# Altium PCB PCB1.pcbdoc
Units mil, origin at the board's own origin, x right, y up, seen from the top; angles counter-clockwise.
Board outline 4214 x 1585.88 mil, 2 copper layers (Top Layer, Bottom Layer); 84 components, 62 nets, 353 pads, 138 vias.
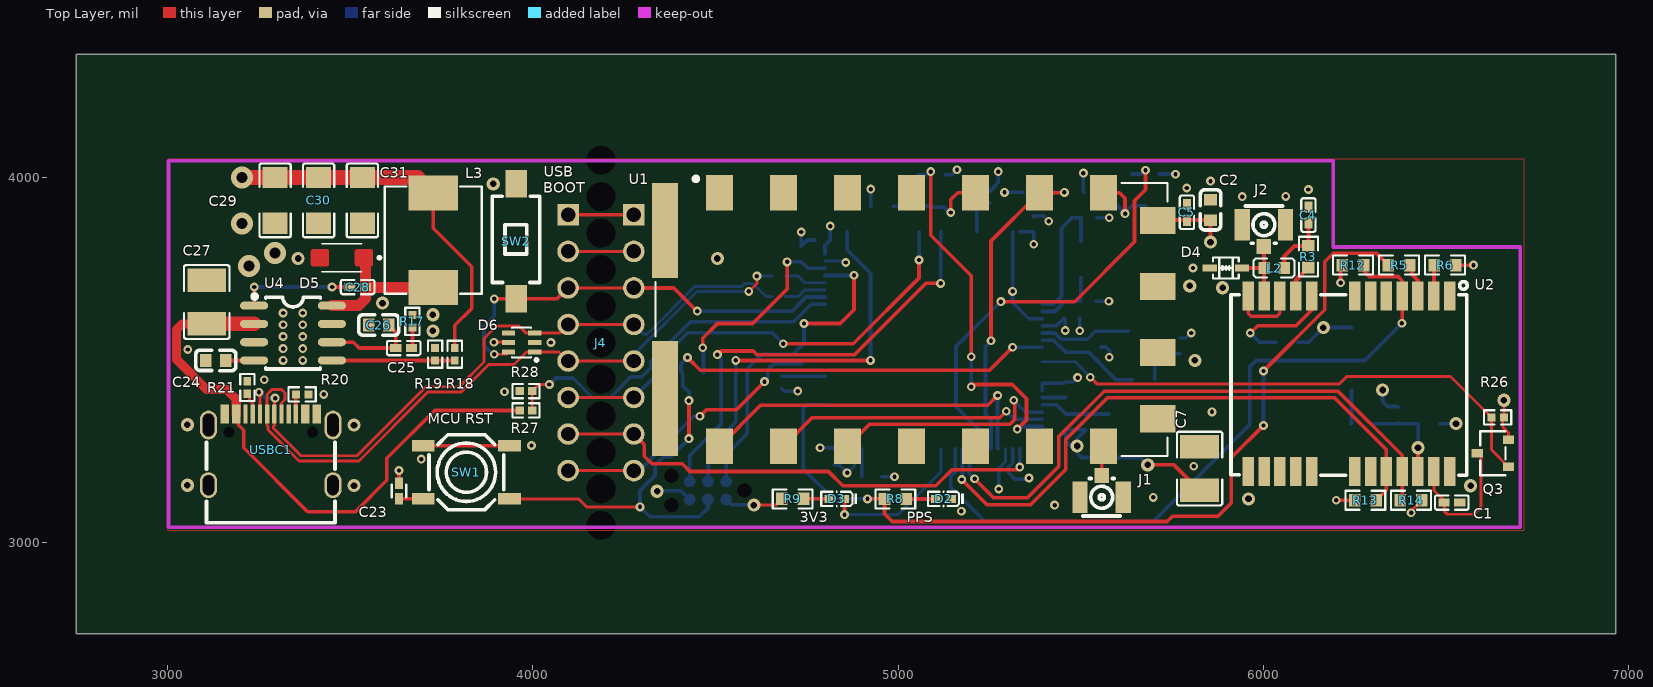
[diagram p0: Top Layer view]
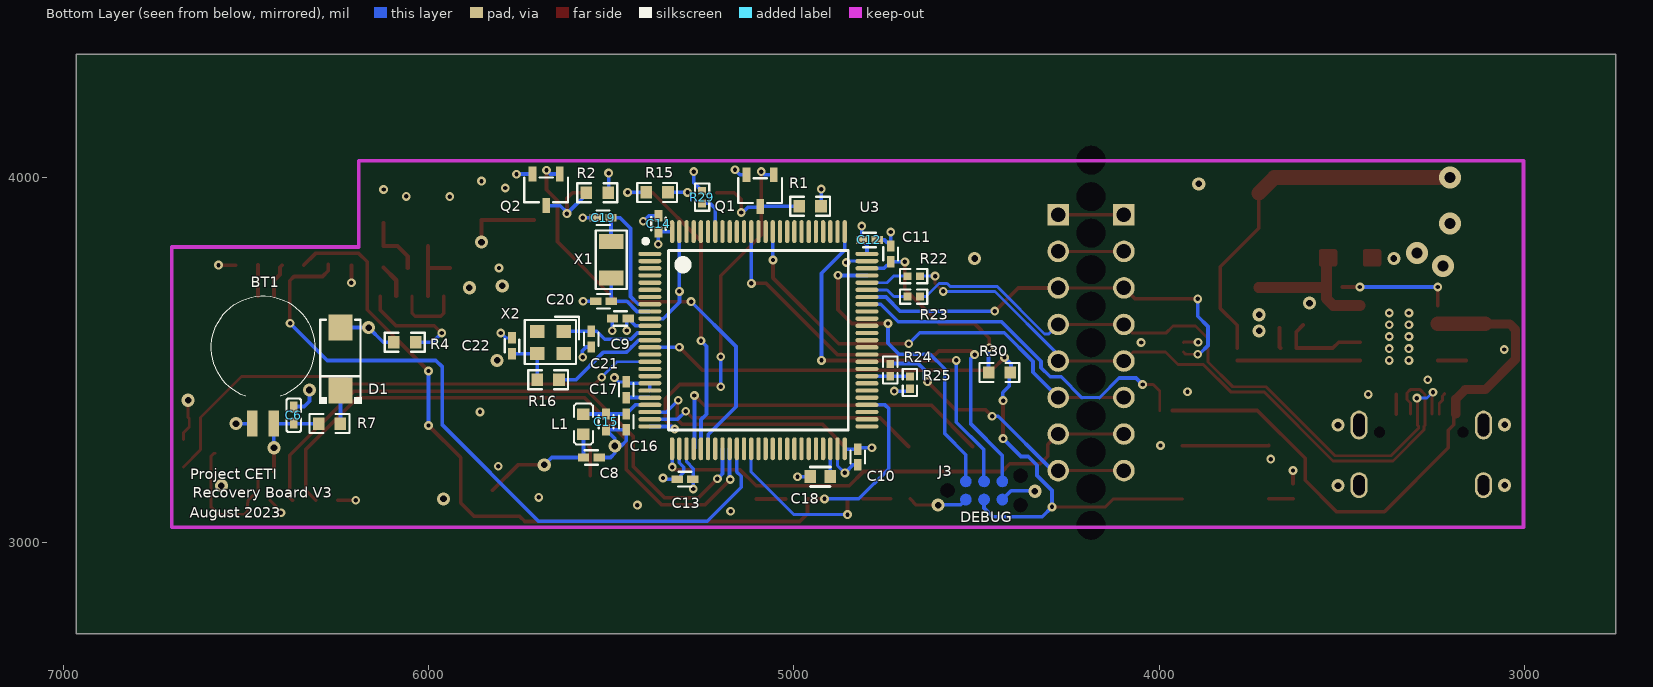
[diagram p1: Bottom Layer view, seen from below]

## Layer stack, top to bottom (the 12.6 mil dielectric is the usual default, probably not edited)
Top Layer: signal copper (thickness not stored)
Dielectric: dielectric 12.6, FR-4, Dk 4.8
Bottom Layer: signal copper (thickness not stored)

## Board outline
6964,2750 2750,2750 2750,4335.88 6964,4335.88

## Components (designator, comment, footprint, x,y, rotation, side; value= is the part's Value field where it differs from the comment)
BT1 "MS621FE-FL11E" MS621FE-FL11E 6453,3325 r180 bottom
C1 "100nF" C0402 6515.46,3109 r180 top
C2 "10uF" C0603 5855,3910 r270 top
C4 "47pF" C0402 6123,3896 r270 top
C5 "100nF" C0402 5790.46,3903.46 r270 top
C6 "1uF" C0402 6369,3348 r270 bottom
C7 "100uF" C1210 5825,3202 r90 top
C8 "100nF" C0402 5554.33,3232.25 r0 bottom
C9 "100nF" C0402 5474.79,3612.79 r180 bottom
C10 "100nF" C0402 4824.79,3233.79 r90 bottom
C11 "100nF" C0402 4734.79,3789.79 r270 bottom
C12 "100nF" C0402 4792.79,3827.79 r0 bottom
C13 "100nF" C0402 5298,3173 r180 bottom
C14 "100nF" C0402 5370.33,3872.25 r270 bottom
C15 "1uF" C0402 5513.79,3329.79 r90 bottom
C16 "10nF" C0402 5458.79,3329.79 r90 bottom
C17 "100nF" C0402 5458.79,3417.79 r270 bottom
C18 "4.7uF" C0603 4927.79,3179.79 r180 bottom
C19 "15pF" C0402 5521.79,3888.79 r180 bottom
C20 "15pF" C0402 5520.79,3659.79 r180 bottom
C21 "6pF" C0402 5554.38,3556.2 r90 bottom
C22 "6pF" C0402 5771.38,3538.2 r270 bottom
C23 "100nF" C0402 3633.16,3140.54 r270 top
C24 "CC0603KRX7R9BB822" C0603 3132,3498 r0 top
C25 "0402B102K500NT" C0402 3646,3532 r180 top
C26 "0603CG6R8C500NT" C0603 3578,3595 r0 top
C27 "GCM32ER71C226KE19L" C1210 3107,3658 r270 top
C28 "V104K0402X5R250NBT" C0402 3520,3699 r0 top
C29 "CL31A476MPHNNNE" C1206 3294,3936 r90 top
C30 "CL31A476MPHNNNE" C1206 3413,3936 r90 top
C31 "CL31A476MPHNNNE" C1206 3533,3936 r90 top
D1 "SS14L" SMA_L4.4-W2.6-LS5.0-RD 6241,3502 r90 bottom
D2 "16-213/BHC-ZL1M2B6Y/3T" LED0402-RD_BLUE 5124,3119 r180 top
D3 "16-213/SDRC/S530-A3/TR8" LED0402-RD 4831.71,3119 r180 top
D4 "LESD3Z5.0CMT1G" SOD-323_L1.8-W1.3-LS2.5-BI 5897,3751 r0 top
D5 "SS24FL" SODFL3617X108N 3477,3779 r180 top
D6 "PUSB2X4Y-N" SOT-363_L2.1-W1.3-P0.65-LS2.3-BL 3969,3547 r90 top
J1 "1909763-1" ANT-SMD_1909763-1 5557,3153 r0 top
J2 "1909763-1" ANT-SMD_1909763-1 6001,3840 r180 top
J3 "TC2030-IDC-NL" TC2030-IDC-NL 4529,3167 r180 bottom
J4 "CASTELLATION-0.05&quot;-W/-TH" "CASTELLATION-0.05\"-W/-TH" 4186.1,3946.51 r0 top
L1 "Ferrite Bead" L0603 5575.81,3323.68 r270 bottom
L2 "MPZ1608D300BTD25" L0603 6029,3751 r0 top
L3 "YSPI0730-3R3M" IND-SMD_L7.3-W6.6 3726.94,3827.18 r270 top
Q1 "DMN65D8L-7" SOT-23-3_L3.0-W1.7-P0.95-LS2.9-BR 5092,3963 r90 bottom
Q2 "DMN65D8L-7" SOT-23-3_L3.0-W1.7-P0.95-LS2.9-BR 5678,3965 r90 bottom
Q3 "SSM3J332R,LF" SOT-23F_L2.9-W1.8-P0.95-LS2.4-BR 6628,3244 r0 top
R1 "1k" R0603 4955,3920 r180 bottom
R2 "1k" R0603 5538,3957 r180 bottom
R3 "10" R0603 6123,3782 r270 top
R4 "10k" R0603 6065,3548 r0 bottom
R5 "0 Ohm" R0603 6371,3759 r180 top
R6 "75k" R0603 6497,3759 r0 top
R7 "1k" R0603 6271,3325 r180 bottom
R8 "100" R0603 4992.02,3118.75 r0 top
R9 "140" R0603 4711,3119 r0 top
R12 "75k" R0603 6245,3759 r180 top
R13 "75k" R0603 6279,3115 r180 top
R14 "75k" R0603 6404,3115 r0 top
R15 "10k" R0603 5374,3958 r180 bottom
R16 "0 Ohm" R0603 5672.38,3445.2 r180 bottom
R17 "43.2k" R0402 3670,3605 r270 top
R18 "10.2k" R0402 3786.04,3514.96 r90 top
R19 "3.24k" R0402 3732,3515 r270 top
R20 "5.1k" R0402 3368,3405 r180 top
R21 "5.1k" R0402 3218,3424 r270 top
R22 "27" R0402 4671.79,3728.79 r180 bottom
R23 "27" R0402 4671.79,3672.79 r0 bottom
R24 "10k" R0402 4735.99,3471.68 r90 bottom
R25 "4.22k" R0402 4681.99,3437.49 r90 bottom
R26 "15k" R0402 6641,3342 r0 top
R27 "42.2k" R0402 3981,3361 r180 top
R28 "82k" R0402 3981,3414 r0 top
R29 "10k" R0402 5251,3945 r270 bottom
R30 "10k" R0603 4437,3465 r180 bottom
SW1 "TS5215A 250gf" SW-SMD_4P-L5.2-W5.2-P3.70-LS6.4 3817.7,3192 r180 top
SW2 "TS-1101-C-W" SW-SMD_L6.0-W3.3-LS8.0 3954,3824 r270 top
U1 "DRA818V" DORJI_DRA818V 5036,3610 r0 top
U2 "NEO-M9N-00B" GPSM-SMD_24P-L16.0-W12.2-P1.10-BL 6234,3434 r90 top
U3 "STM32U575VGT6" LQFP-100_L14.0-W14.0-P0.50-LS16.0-BL 5096.78,3553.44 r270 bottom
U4 "TPS54331DR" SOIC-8_L5.0-W4.0-P1.27-LS6.0-BL 3343,3573 r270 top
USBC1 "TYPE-C-31-M-12" USB-C_SMD-TYPE-C-31-M-12 3282,3254 r0 top
X1 "32.768kHz" OSC-SMD_L3.2-W1.5 5499.8,3773.72 r270 bottom
X2 "16MHz" CRYSTAL-SMD_4P-L2.5-W2.0-BL-A 5665.63,3547.21 r0 bottom

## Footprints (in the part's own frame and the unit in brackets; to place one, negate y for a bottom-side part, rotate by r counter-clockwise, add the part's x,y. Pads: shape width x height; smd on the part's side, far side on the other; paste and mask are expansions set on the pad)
ANT-SMD_1909763-1 [mm]
  rect 1x1.05 smd paste+0 mask+0.051: 1(0,0.751)
  rect 1.05x2.2 smd paste+0 mask+0.051: 2(-1.5,-0.751) 2(1.5,-0.751)
  silkscreen extent -1.3,-2.05 1.3,0.55
C0402 [mm]
  rect 0.79x0.54 smd paste-100 mask+0.051: 1(-0.545,0) 2(0.545,0)
  silkscreen extent -1.17,-0.5 1.17,0.5
C0603 [mm]
  rect 0.8x0.9 smd paste+0 mask+0.051: 1(-0.7,0) 2(0.7,0)
  silkscreen extent -1.41,-0.71 1.39,0.72
C1206 [mm]
  rect 1.485x1.728 smd paste-100 mask+0.051: 1(-1.593,0) 2(1.593,0)
  silkscreen extent -2.56,-1.09 2.56,1.09
C1210 [mm]
  rect 1.635x2.7 smd paste-100 mask+0.051: 1(-1.517,0) 2(1.517,0)
  silkscreen extent -2.56,-1.58 2.56,1.58
"CASTELLATION-0.05\"-W/-TH" [mm]
  rect 1.5x1.5 hole 1 paste+0 mask+0.051: 1(2.286,-1.27) 16(-2.286,-1.27)
  round 1.5 hole 1 paste+0 mask+0.051: 2(2.286,-3.81) 3(2.286,-6.35) 4(2.286,-8.89) 5(2.286,-11.43) 6(2.286,-13.97) 7(2.286,-16.51) 8(2.286,-19.05) 9(-2.286,-19.05) 10(-2.286,-16.51) 11(-2.286,-13.97) 12(-2.286,-11.43) 13(-2.286,-8.89) 14(-2.286,-6.35) 15(-2.286,-3.81)
  Multi-Layer board cut-out: 1,0 0.901,0.434 0.623,0.782 0.223,0.975 -0.223,0.975 -0.623,0.782 -0.901,0.434 -1,0 -1,0 -0.901,-0.434 -0.623,-0.782 -0.223,-0.975 0.223,-0.975 0.623,-0.782 0.901,-0.434 1,0
  Multi-Layer board cut-out: 1,-2.54 0.901,-2.106 0.623,-1.758 0.223,-1.565 -0.223,-1.565 -0.623,-1.758 -0.901,-2.106 -1,-2.54 -1,-2.54 -0.901,-2.974 -0.623,-3.322 -0.223,-3.515 0.223,-3.515 0.623,-3.322 0.901,-2.974 1,-2.54
  Multi-Layer board cut-out: 1,-7.62 0.901,-7.186 0.623,-6.838 0.223,-6.645 -0.223,-6.645 -0.623,-6.838 -0.901,-7.186 -1,-7.62 -1,-7.62 -0.901,-8.054 -0.623,-8.402 -0.223,-8.595 0.223,-8.595 0.623,-8.402 0.901,-8.054 1,-7.62
  Multi-Layer board cut-out: 1,-5.08 0.901,-4.646 0.623,-4.298 0.223,-4.105 -0.223,-4.105 -0.623,-4.298 -0.901,-4.646 -1,-5.08 -1,-5.08 -0.901,-5.514 -0.623,-5.862 -0.223,-6.055 0.223,-6.055 0.623,-5.862 0.901,-5.514 1,-5.08
  Multi-Layer board cut-out: 1,-12.7 0.901,-12.266 0.623,-11.918 0.223,-11.725 -0.223,-11.725 -0.623,-11.918 -0.901,-12.266 -1,-12.7 -1,-12.7 -0.901,-13.134 -0.623,-13.482 -0.223,-13.675 0.223,-13.675 0.623,-13.482 0.901,-13.134 1,-12.7
  Multi-Layer board cut-out: 1,-10.16 0.901,-9.726 0.623,-9.378 0.223,-9.185 -0.223,-9.185 -0.623,-9.378 -0.901,-9.726 -1,-10.16 -1,-10.16 -0.901,-10.594 -0.623,-10.942 -0.223,-11.135 0.223,-11.135 0.623,-10.942 0.901,-10.594 1,-10.16
  Multi-Layer board cut-out: 1,-17.78 0.901,-17.346 0.623,-16.998 0.223,-16.805 -0.223,-16.805 -0.623,-16.998 -0.901,-17.346 -1,-17.78 -1,-17.78 -0.901,-18.214 -0.623,-18.562 -0.223,-18.755 0.223,-18.755 0.623,-18.562 0.901,-18.214 1,-17.78
  Multi-Layer board cut-out: 1,-15.24 0.901,-14.806 0.623,-14.458 0.223,-14.265 -0.223,-14.265 -0.623,-14.458 -0.901,-14.806 -1,-15.24 -1,-15.24 -0.901,-15.674 -0.623,-16.022 -0.223,-16.215 0.223,-16.215 0.623,-16.022 0.901,-15.674 1,-15.24
  Multi-Layer board cut-out: 1,-20.32 0.901,-19.886 0.623,-19.538 0.223,-19.345 -0.223,-19.345 -0.623,-19.538 -0.901,-19.886 -1,-20.32 -1,-20.32 -0.901,-20.754 -0.623,-21.102 -0.223,-21.295 0.223,-21.295 0.623,-21.102 0.901,-20.754 1,-20.32
  Multi-Layer board cut-out: 1,2.54 0.901,2.974 0.623,3.322 0.223,3.515 -0.223,3.515 -0.623,3.322 -0.901,2.974 -1,2.54 -1,2.54 -0.901,2.106 -0.623,1.758 -0.223,1.565 0.223,1.565 0.623,1.758 0.901,2.106 1,2.54
  Multi-Layer board cut-out: 1,-22.86 0.901,-22.426 0.623,-22.078 0.223,-21.885 -0.223,-21.885 -0.623,-22.078 -0.901,-22.426 -1,-22.86 -1,-22.86 -0.901,-23.294 -0.623,-23.642 -0.223,-23.835 0.223,-23.835 0.623,-23.642 0.901,-23.294 1,-22.86
CRYSTAL-SMD_4P-L2.5-W2.0-BL-A [mm]
  rect 1x0.9 smd paste+0 mask+0.051: 1(-0.925,-0.775) 2(0.925,-0.775) 3(0.925,0.775) 4(-0.925,0.775)
  silkscreen extent -1.98,-1.78 1.8,1.5
DORJI_DRA818V [mm]
  rect 1.88x2.47 smd paste+0 mask+0.051: 1(-13.35,8.825) 2(-8.9,8.825) 3(-4.45,8.825) 4(0,8.825) 5(4.45,8.825) 6(8.9,8.825) 7(13.35,8.825) 12(13.35,-8.825) 13(8.9,-8.825) 14(4.45,-8.825) 15(0,-8.825) 16(-4.45,-8.825) 17(-8.9,-8.825) 18(-13.35,-8.825)
  rect 2.47x1.88 smd paste+0 mask+0.051: 8(17.125,6.9) 9(17.125,2.3) 10(17.125,-2.3) 11(17.125,-6.9)
  rect 1.8x6.6 smd paste+0 mask+0.051: P2(-17.125,6.2)
  rect 1.8x8 smd paste+0 mask+0.051: P3(-17.125,-5.5)
  silkscreen extent -17.8,-9.5 17.8,9.93
GPSM-SMD_24P-L16.0-W12.2-P1.10-BL [mm]
  rect 2x0.8 smd paste+0 mask+0.05: 1(6.1,-7) 2(6.1,-5.9) 3(6.1,-4.8) 4(6.1,-3.7) 5(6.1,-2.6) 6(6.1,-1.5) 7(6.1,-0.4) 8(6.1,2.6) 9(6.1,3.7) 10(6.1,4.8) 11(6.1,5.9) 12(6.1,7) 13(-6.1,7) 14(-6.1,5.9) 15(-6.1,4.8) 16(-6.1,3.7) 17(-6.1,2.6) 18(-6.1,-0.4) 19(-6.1,-1.5) 20(-6.1,-2.6) 21(-6.1,-3.7) 22(-6.1,-4.8) 23(-6.1,-5.9) 24(-6.1,-7)
  silkscreen extent -6.36,-8.23 7.11,8.2
IND-SMD_L7.3-W6.6 [mm]
  rect 2.424x3.42 smd paste+0 mask+0.051: 1(3.278,0) 2(-3.278,0)
  silkscreen extent -3.73,-3.38 3.73,3.38
L0603 [mm]
  rect 0.8x0.864 smd paste-100 mask+0.051: 1(-0.7,0) 2(0.7,0)
  silkscreen extent -1.42,-0.65 1.41,0.67
LED0402-RD [mm]
  rect 0.636x0.54 smd paste-100 mask+0.051: 1(-0.538,0) 2(0.538,0)
  silkscreen extent -1.39,-0.54 1.09,0.54
LED0402-RD_BLUE [mm]
  rect 0.636x0.54 smd paste-100 mask+0.051: 1(-0.538,0) 2(0.538,0)
  silkscreen extent -1.39,-0.54 1.09,0.54
LQFP-100_L14.0-W14.0-P0.50-LS16.0-BL [mm]
  oval 0.3x1.6 smd paste-100 mask+0.051: 1(-6,-7.55) 2(-5.5,-7.55) 3(-5,-7.55) 4(-4.5,-7.55) 5(-4,-7.55) 6(-3.5,-7.55) 7(-3,-7.55) 8(-2.5,-7.55) 9(-2,-7.55) 10(-1.5,-7.55) 11(-1,-7.55) 12(-0.5,-7.55) 13(0,-7.55) 14(0.5,-7.55) 15(1,-7.55) 16(1.5,-7.55) 17(2,-7.55) 18(2.5,-7.55) 19(3,-7.55) 20(3.5,-7.55) 21(4,-7.55) 22(4.5,-7.55) 23(5,-7.55) 24(5.5,-7.55) 25(6,-7.55) 51(6,7.55) 52(5.5,7.55) 53(5,7.55) 54(4.5,7.55) 55(4,7.55) 56(3.5,7.55) 57(3,7.55) 58(2.5,7.55) 59(2,7.55) 60(1.5,7.55) 61(1,7.55) 62(0.5,7.55) 63(0,7.55) 64(-0.5,7.55) 65(-1,7.55) 66(-1.5,7.55) 67(-2,7.55) 68(-2.5,7.55) 69(-3,7.55) 70(-3.5,7.55) 71(-4,7.55) 72(-4.5,7.55) 73(-5,7.55) 74(-5.5,7.55) 75(-6,7.55)
  oval 1.6x0.3 smd paste-100 mask+0.051: 26(7.55,-6) 27(7.55,-5.5) 28(7.55,-5) 29(7.55,-4.5) 30(7.55,-4) 31(7.55,-3.5) 32(7.55,-3) 33(7.55,-2.5) 34(7.55,-2) 35(7.55,-1.5) 36(7.55,-1) 37(7.55,-0.5) 38(7.55,0) 39(7.55,0.5) 40(7.55,1) 41(7.55,1.5) 42(7.55,2) 43(7.55,2.5) 44(7.55,3) 45(7.55,3.5) 46(7.55,4) 47(7.55,4.5) 48(7.55,5) 49(7.55,5.5) 50(7.55,6) 76(-7.55,6) 77(-7.55,5.5) 78(-7.55,5) 79(-7.55,4.5) 80(-7.55,4) 81(-7.55,3.5) 82(-7.55,3) 83(-7.55,2.5) 84(-7.55,2) 85(-7.55,1.5) 86(-7.55,1) 87(-7.55,0.5) 88(-7.55,0) 89(-7.55,-0.5) 90(-7.55,-1) 91(-7.55,-1.5) 92(-7.55,-2) 93(-7.55,-2.5) 94(-7.55,-3) 95(-7.55,-3.5) 96(-7.55,-4) 97(-7.55,-4.5) 98(-7.55,-5) 99(-7.55,-5.5) 100(-7.55,-6)
  silkscreen extent -7.03,-8 6.25,6.25
MS621FE-FL11E [mm]
  rect 0.75x1.8 smd paste+0 mask+0.051: +(0.75,0) -(-0.75,0)
  silkscreen extent -3.59,1.9 3.59,8.88
OSC-SMD_L3.2-W1.5 [mm]
  rect 1.05x1.7 smd paste+0 mask+0.051: 1(-1.275,0) 2(1.275,0)
  silkscreen extent -2.03,-1.08 2.03,1.08
R0402 [mm]
  rect 0.566x0.54 smd paste-100 mask+0.051: 1(-0.433,0) 2(0.433,0)
  silkscreen extent -0.94,-0.5 0.94,0.5
R0603 [mil]
  rect 31.75x34.02 smd paste-3937.01 mask+2: 1(-29.66,0) 2(29.66,0)
  silkscreen extent -55,-26 55,26
SMA_L4.4-W2.6-LS5.0-RD [mm]
  rect 1.8x1.7 smd paste+0 mask+0.051: 1(-2.192,0) 2(2.192,0)
  silkscreen extent -3.11,-1.48 2.73,1.48
SOD-323_L1.8-W1.3-LS2.5-BI [mm]
  rect 0.985x0.49 smd paste+0 mask+0.051: 1(-1.118,0) 2(1.118,0)
  silkscreen extent -0.9,-0.73 0.9,0.73
SODFL3617X108N [mil]
  Top Layer region: -84.84,17.12 -84.8,17.81 -84.67,18.49 -84.47,19.15 -84.18,19.78 -83.83,20.37 -83.4,20.91 -82.92,21.4 -82.37,21.82 -81.78,22.18 -81.15,22.46 -80.5,22.67 -79.82,22.79 -79.13,22.83 -41.33,22.83 -40.65,22.79 -39.97,22.67 -39.31,22.46 -38.68,22.18 -38.09,21.82 -37.55,21.4 -37.06,20.91 -36.64,20.37 -36.28,19.78 -36,19.15 -35.79,18.49 -35.67,17.81 -35.63,17.12 -35.63,-17.13 -35.67,-17.82 -35.79,-18.5 -36,-19.15 -36.28,-19.78 -36.64,-20.37 -37.06,-20.92 -37.55,-21.4 -38.09,-21.83 -38.68,-22.18 -39.31,-22.47 -39.97,-22.67 -40.65,-22.8 -41.33,-22.84 -79.13,-22.84 -79.82,-22.8 -80.5,-22.67 -81.15,-22.47 -81.78,-22.18 -82.37,-21.83 -82.92,-21.4 -83.4,-20.92 -83.83,-20.37 -84.18,-19.78 -84.47,-19.15 -84.67,-18.5 -84.8,-17.82 -84.84,-17.13
  Top Layer region: 35.63,17.12 35.68,17.81 35.8,18.49 36.01,19.15 36.29,19.78 36.64,20.37 37.07,20.91 37.56,21.4 38.1,21.82 38.69,22.18 39.32,22.46 39.98,22.67 40.65,22.79 41.34,22.83 79.14,22.83 79.83,22.79 80.5,22.67 81.16,22.46 81.79,22.18 82.38,21.82 82.92,21.4 83.41,20.91 83.84,20.37 84.19,19.78 84.48,19.15 84.68,18.49 84.8,17.81 84.85,17.12 84.85,-17.13 84.8,-17.82 84.68,-18.5 84.48,-19.15 84.19,-19.78 83.84,-20.37 83.41,-20.92 82.92,-21.4 82.38,-21.83 81.79,-22.18 81.16,-22.47 80.5,-22.67 79.83,-22.8 79.14,-22.84 41.34,-22.84 40.65,-22.8 39.98,-22.67 39.32,-22.47 38.69,-22.18 38.1,-21.83 37.56,-21.4 37.07,-20.92 36.64,-20.37 36.29,-19.78 36.01,-19.15 35.8,-18.5 35.68,-17.82 35.63,-17.13
  silkscreen extent -106,-38 54,38
SOIC-8_L5.0-W4.0-P1.27-LS6.0-BL [mil]
  oval 22.38x76.78 smd paste+0 mask+2: 1(-75,-106.5) 2(-25,-106.5) 3(25,-106.5) 4(75,-106.5) 5(75,106.5) 6(25,106.5) 7(-25,106.5) 8(-75,106.5)
  silkscreen extent -106,-111 98,75
SOT-23-3_L3.0-W1.7-P0.95-LS2.9-BR [mil]
  rect 40.85x20.95 smd paste+0 mask+2: 1(43.36,-37.4) 2(43.36,37.4) 3(-43.36,0)
  silkscreen extent -34,-60 34,60
SOT-23F_L2.9-W1.8-P0.95-LS2.4-BR [mm]
  rect 0.785x0.595 smd paste+0 mask+0.051: 1(1.092,-0.95) 2(1.092,0.95) 3(-1.092,0)
  silkscreen extent -0.88,-1.53 0.88,1.53
SOT-363_L2.1-W1.3-P0.65-LS2.3-BL [mm]
  rect 0.35x0.916 smd paste+0 mask+0.051: 1(-0.65,-0.908) 2(0,-0.908) 3(0.65,-0.908) 4(0.65,0.908) 5(0,0.908) 6(-0.65,0.908)
  silkscreen extent -1.31,-1.13 1.05,0.66
SW-SMD_4P-L5.2-W5.2-P3.70-LS6.4 [mm]
  rect 1.58x0.8 smd paste+0 mask+0.051: 1(-3,1.85) 2(3,1.85) 3(-3,-1.85) 4(3,-1.85)
  silkscreen extent -2.6,-2.6 2.6,2.6
SW-SMD_L6.0-W3.3-LS8.0 [mm]
  rect 1.9x1.5 smd paste+0 mask+0.051: 1(-4,0) 2(4,0)
  silkscreen extent -3.14,-1.67 2.86,1.63
TC2030-IDC-NL [mil]
  Top Layer region: -15.5,0 -15.39,1.87 -15.05,3.71 -14.49,5.5 -13.72,7.2 -12.76,8.8 -11.6,10.28 -10.28,11.6 -8.8,12.76 -7.2,13.72 -5.5,14.49 -3.71,15.05 -1.87,15.39 0,15.5 1.87,15.39 3.71,15.05 5.5,14.49 7.2,13.72 8.8,12.76 10.28,11.6 11.6,10.28 12.76,8.8 13.72,7.2 14.49,5.5 15.05,3.71 15.39,1.87 15.5,0 15.39,-1.87 15.05,-3.71 14.49,-5.5 13.72,-7.2 12.76,-8.8 11.6,-10.28 10.28,-11.6 8.8,-12.76 7.2,-13.72 5.5,-14.49 3.71,-15.05 1.87,-15.39 0,-15.5 -1.87,-15.39 -3.71,-15.05 -5.5,-14.49 -7.2,-13.72 -8.8,-12.76 -10.28,-11.6 -11.6,-10.28 -12.76,-8.8 -13.72,-7.2 -14.49,-5.5 -15.05,-3.71 -15.39,-1.87
  Top Layer region: -15.5,-50 -15.39,-48.13 -15.05,-46.29 -14.49,-44.5 -13.72,-42.8 -12.76,-41.19 -11.6,-39.72 -10.28,-38.4 -8.8,-37.24 -7.2,-36.28 -5.5,-35.51 -3.71,-34.95 -1.87,-34.61 0,-34.5 1.87,-34.61 3.71,-34.95 5.5,-35.51 7.2,-36.28 8.8,-37.24 10.28,-38.4 11.6,-39.72 12.76,-41.19 13.72,-42.8 14.49,-44.5 15.05,-46.29 15.39,-48.13 15.5,-50 15.39,-51.87 15.05,-53.71 14.49,-55.5 13.72,-57.2 12.76,-58.8 11.6,-60.28 10.28,-61.6 8.8,-62.76 7.2,-63.72 5.5,-64.49 3.71,-65.05 1.87,-65.39 0,-65.5 -1.87,-65.39 -3.71,-65.05 -5.5,-64.49 -7.2,-63.72 -8.8,-62.76 -10.28,-61.6 -11.6,-60.28 -12.76,-58.8 -13.72,-57.2 -14.49,-55.5 -15.05,-53.71 -15.39,-51.87
  Top Layer region: 34.5,0 34.61,1.87 34.95,3.71 35.51,5.5 36.28,7.2 37.24,8.8 38.4,10.28 39.72,11.6 41.19,12.76 42.8,13.72 44.5,14.49 46.29,15.05 48.13,15.39 50,15.5 51.87,15.39 53.71,15.05 55.5,14.49 57.2,13.72 58.8,12.76 60.28,11.6 61.6,10.28 62.76,8.8 63.72,7.2 64.49,5.5 65.05,3.71 65.39,1.87 65.5,0 65.39,-1.87 65.05,-3.71 64.49,-5.5 63.72,-7.2 62.76,-8.8 61.6,-10.28 60.28,-11.6 58.8,-12.76 57.2,-13.72 55.5,-14.49 53.71,-15.05 51.87,-15.39 50,-15.5 48.13,-15.39 46.29,-15.05 44.5,-14.49 42.8,-13.72 41.19,-12.76 39.72,-11.6 38.4,-10.28 37.24,-8.8 36.28,-7.2 35.51,-5.5 34.95,-3.71 34.61,-1.87
  Top Layer region: 34.5,-50 34.61,-48.13 34.95,-46.29 35.51,-44.5 36.28,-42.8 37.24,-41.19 38.4,-39.72 39.72,-38.4 41.19,-37.24 42.8,-36.28 44.5,-35.51 46.29,-34.95 48.13,-34.61 50,-34.5 51.87,-34.61 53.71,-34.95 55.5,-35.51 57.2,-36.28 58.8,-37.24 60.28,-38.4 61.6,-39.72 62.76,-41.19 63.72,-42.8 64.49,-44.5 65.05,-46.29 65.39,-48.13 65.5,-50 65.39,-51.87 65.05,-53.71 64.49,-55.5 63.72,-57.2 62.76,-58.8 61.6,-60.28 60.28,-61.6 58.8,-62.76 57.2,-63.72 55.5,-64.49 53.71,-65.05 51.87,-65.39 50,-65.5 48.13,-65.39 46.29,-65.05 44.5,-64.49 42.8,-63.72 41.19,-62.76 39.72,-61.6 38.4,-60.28 37.24,-58.8 36.28,-57.2 35.51,-55.5 34.95,-53.71 34.61,-51.87
  Top Layer region: 84.5,0 84.61,1.87 84.95,3.71 85.51,5.5 86.28,7.2 87.24,8.8 88.4,10.28 89.72,11.6 91.19,12.76 92.8,13.72 94.5,14.49 96.29,15.05 98.13,15.39 100,15.5 101.87,15.39 103.71,15.05 105.5,14.49 107.2,13.72 108.8,12.76 110.28,11.6 111.6,10.28 112.76,8.8 113.72,7.2 114.49,5.5 115.05,3.71 115.39,1.87 115.5,0 115.39,-1.87 115.05,-3.71 114.49,-5.5 113.72,-7.2 112.76,-8.8 111.6,-10.28 110.28,-11.6 108.8,-12.76 107.2,-13.72 105.5,-14.49 103.71,-15.05 101.87,-15.39 100,-15.5 98.13,-15.39 96.29,-15.05 94.5,-14.49 92.8,-13.72 91.19,-12.76 89.72,-11.6 88.4,-10.28 87.24,-8.8 86.28,-7.2 85.51,-5.5 84.95,-3.71 84.61,-1.87
  Top Layer region: 84.5,-50 84.61,-48.13 84.95,-46.29 85.51,-44.5 86.28,-42.8 87.24,-41.19 88.4,-39.72 89.72,-38.4 91.19,-37.24 92.8,-36.28 94.5,-35.51 96.29,-34.95 98.13,-34.61 100,-34.5 101.87,-34.61 103.71,-34.95 105.5,-35.51 107.2,-36.28 108.8,-37.24 110.28,-38.4 111.6,-39.72 112.76,-41.19 113.72,-42.8 114.49,-44.5 115.05,-46.29 115.39,-48.13 115.5,-50 115.39,-51.87 115.05,-53.71 114.49,-55.5 113.72,-57.2 112.76,-58.8 111.6,-60.28 110.28,-61.6 108.8,-62.76 107.2,-63.72 105.5,-64.49 103.71,-65.05 101.87,-65.39 100,-65.5 98.13,-65.39 96.29,-65.05 94.5,-64.49 92.8,-63.72 91.19,-62.76 89.72,-61.6 88.4,-60.28 87.24,-58.8 86.28,-57.2 85.51,-55.5 84.95,-53.71 84.61,-51.87
  Multi-Layer board cut-out: -69.5,-25 -67.57,-16.54 -62.16,-9.75 -54.34,-5.99 -45.66,-5.99 -37.84,-9.75 -32.43,-16.54 -30.5,-25 -30.5,-25 -32.43,-33.46 -37.84,-40.25 -45.66,-44.01 -54.34,-44.01 -62.16,-40.25 -67.57,-33.46 -69.5,-25
  Multi-Layer board cut-out: 130.5,15 132.43,23.46 137.84,30.25 145.66,34.01 154.34,34.01 162.16,30.25 167.57,23.46 169.5,15 169.5,15 167.57,6.54 162.16,-0.25 154.34,-4.01 145.66,-4.01 137.84,-0.25 132.43,6.54 130.5,15
  Multi-Layer board cut-out: 130.5,-65 132.43,-56.54 137.84,-49.75 145.66,-45.99 154.34,-45.99 162.16,-49.75 167.57,-56.54 169.5,-65 169.5,-65 167.57,-73.46 162.16,-80.25 154.34,-84.01 145.66,-84.01 137.84,-80.25 132.43,-73.46 130.5,-65
USB-C_SMD-TYPE-C-31-M-12 [mm]
  oval 1.2x2 hole 0.8 slot 1.6 at 90 deg paste+0 mask+0.051: 0(-4.325,1.706) 1(4.325,1.706)
  oval 1.2x1.8 hole 0.8 slot 1.4 at 90 deg paste+0 mask+0.051: 2(4.325,-2.474) 3(-4.325,-2.474)
  rect 0.3x1.3 smd paste-100 mask+0.051: A1(-3.35,2.474) A4(-2.55,2.474) A5(-1.25,2.474) A6(-0.25,2.474) A7(0.25,2.474) A8(1.25,2.474) A9(2.55,2.474) A12(3.35,2.474) B1(3.05,2.474) B4(2.25,2.474) B5(1.75,2.474) B6(0.75,2.474) B7(-0.75,2.474) B8(-1.75,2.474) B9(-2.25,2.474) B12(-3.05,2.474)
  Multi-Layer board cut-out: -2.525,1.206 -2.562,1.368 -2.666,1.499 -2.816,1.571 -2.983,1.571 -3.134,1.499 -3.238,1.368 -3.275,1.206 -3.275,1.206 -3.238,1.043 -3.134,0.912 -2.983,0.84 -2.816,0.84 -2.666,0.912 -2.562,1.043 -2.525,1.206
  Multi-Layer board cut-out: 3.275,1.206 3.238,1.368 3.134,1.499 2.983,1.571 2.816,1.571 2.666,1.499 2.562,1.368 2.525,1.206 2.525,1.206 2.562,1.043 2.666,0.912 2.816,0.84 2.983,0.84 3.134,0.912 3.238,1.043 3.275,1.206
  silkscreen extent -4.47,-5.09 4.47,0.49

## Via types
v1: diameter 24, hole 12, Top Layer to Bottom Layer, 87 vias
v2: diameter 36, hole 18, Top Layer to Bottom Layer, 25 vias
v3: diameter 24.02, hole 12.01, Top Layer to Bottom Layer, 22 vias
v4: diameter 60, hole 30, Top Layer to Bottom Layer, 4 vias

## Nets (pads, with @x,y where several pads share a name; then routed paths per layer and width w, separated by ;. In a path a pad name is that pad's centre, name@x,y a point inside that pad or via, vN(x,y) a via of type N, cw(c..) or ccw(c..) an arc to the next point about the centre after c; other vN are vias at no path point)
3V3_LED_NEN: D3.1 U3.37 | length 418.9
  Top Layer w10: D3.1 4853,3118.9 v1(4853,3076)
  Bottom Layer w8: v1(4853,3076) 5000,3076 5117,3193 5117,3255.66 U3.37
$1N2852: C22.2 R16.1 X2.3 | length 140
  Bottom Layer w10: R16.1@5702.03,3446.05 X2.3 5702.08,3516.74 C22.2
$1N3176: C23.2 SW1.2 | length 66.5
  Top Layer w10: C23.2 3633.25,3119.17 SW1.2
$1N3665: R22.1 U3.71 | length 116.5
  Bottom Layer w8: R22.1@4690.83,3728.96 4726.41,3728.96 4744.58,3710.79 U3.71@4799.79,3710.79
$1N3668: R23.2 U3.70 | length 116.5
  Bottom Layer w8: R23.2@4690.58,3673.07 4726.16,3673.07 4744.33,3691.24 U3.70
$1N5732: R29.2 U3.94 | length 105.1
  Bottom Layer w10: U3.94 5214.89,3913.89 5228.96,3927.96 R29.2
$2N1279: C4.2 L2.2 R3.1 | length 173.9
  Top Layer w11.54: L2.2 6056.56,3782.55 6085,3811 R3.1@6122.34,3811 ; C4.2 R3.1 ; R3.1@6122.34,3811 R3.1 ; R3.1@6122.34,3811 R3.1
$2N1313: R6.1 U2.2 | length 85.1
  Top Layer w10: U2.2@6466.72,3674.16 R6.1@6466.72,3759.24
$2N1327: D1.1 R7.2 | length 91.3
  Bottom Layer w10: R7.2@6239.5,3325 6241,3326.5 D1.1
$2N1329: D2.2 R8.2 | length 81.2
  Top Layer w10: R8.2 5102.56,3118.75 D2.2
$3N108: D3.2 R9.2 | length 75.1
  Top Layer w10: R9.2@4735.37,3119 D3.2
$3N376: C24.2 U4.4 | length 76.9
  Top Layer w10: C24.2 U4.4
$3N888: C25.2 C26.2 U4.6 | length 252.5
  Top Layer w10: U4.6 3508.15,3548 3524.15,3532 C25.2 3624.54,3576.02 C26.2
$3N1536: C28.1 U4.1 | length 312.7
  Top Layer w10: U4.1 3236.5,3698.5 v1(3237,3699) ; v1(3449.97,3699) C28.1
  Bottom Layer w10: v1(3237,3699) v1(3449.97,3699)
$3N1543: C28.2 L3.1 U4.8 | length 396.4
  Top Layer w30: U4.8 3523,3648 3542,3667 C28.2@3542,3698.46 ; 3541.23,3777 3542,3776.23 C28.2@3542,3698.46 ; C28.2 C28.2@3542,3698.46 ; C28.2@3542,3698.12 L3.1
$3N1649: R18.1 R19.2 U4.5 | length 336.6
  Top Layer w10: U4.5 3683.04,3498 R19.2 ; R19.2 3786,3497.96 R18.1
$3N1660: C25.1 R17.2 | length 57
  Top Layer w10: C25.1 3670,3534.54 R17.2
$3N2636: R20.2 USBC1.B5 | length 53.6
  Top Layer w10: USBC1.B5@3350.96,3351.41 R20.2
$3N2685: R21.2 USBC1.A5 | length 61.7
  Top Layer w8: R21.2 3224,3400.96 3224,3389 3232.79,3380.21 USBC1.A5
+3V3: C2.2 C5.2 C7.1 C8.2 C9.2 C10.2 C11.2 C12.2 C13.2 C14.2 C29.2 C30.2 C31.2 D1.2 D6.5 J4.1 J4.16 L1.2 L3.2 Q3.2 R1.2 R2.2 R4.2 R6.2 R9.1 R12.2 R13.2 R14.2 R15.2 R18.2 R26.2 R30.1 U1.8 U3.11 U3.28 U3.50 U3.73 U3.75 U3.100 | length 3696.9
  Top Layer w8: v1(3893,3548) 3932.25,3548 D6.5 ; v1(6404,3081) 6404,3085.34 R14.2 ; v2(6658,3389) R26.2 6655,3338.96 6655,3316 6671.01,3299.99 Q3.2
  Top Layer w9: J4.16@4095.1,3896.51 J4.1@4275.1,3896.51 ; v2(4605,3102) 4664.34,3102 R9.1 ; v1(6199,3115) R13.2
  Top Layer w10: L3.2 3726.94,3859.73 3832.04,3754.63 3832.04,3640.49 3786.04,3594.49 R18.2 ; v1(4465,3533) 4465,3559 4505,3599 4602,3599 4695.79,3692.79 v3(4695.79,3767.79) ; v2(5683,3212) 5755.26,3212 C7.1 ; C5.2 5710.56,3882 5711,3882.44 C2.2 v2(5855,3822) ; v1(6211,3711) R12.2@6211,3759 ; R6.2@6528.3,3759 v1(6575,3759)
  Top Layer w40: v4(3203,3999) C29.2@3294,3998.99 ; C29.2 3532.7,3998.7 C31.2@3533,3998.99 ; C31.2 3684.48,3998.7 L3.2
  Bottom Layer w9: C13.2@5275,3175.46 5275,3202 5293.63,3220.63 U3.28
  Bottom Layer w10: v1@4466,3531 4466.66,3530.34 R30.1 ; 4529,3117 4543,3103 4604,3103 v2(4605,3102) ; v3(4695.79,3767.79) 4734.24,3767.79 C11.2 4752.83,3750.29 U3.73 ; v3(4786,3259) 4821.04,3259 C10.2 U3.50@4860.56,3255.25 ; U3.75 4799.54,3813.09 C12.2 4813.79,3828.25 v3(4813.79,3865.79) ; v1(4925,3967) 4925,3920.34 R1.2 ; v3(5275,3146) C13.2@5275,3174.54 ; C13.2@5275,3175.46 C13.2@5275,3174.54 ; C13.2 C13.2@5275,3174.54 ; v1(5291,3958) R15.2@5342.7,3958 ; U3.100@5333,3850.79 C14.2 5370.79,3850.33 v3(5370.79,3815.79) ; U3.11 5433.34,3592.81 C9.2 ; C9.2@5454.33,3612.79 5456.79,3610.33 v3@5456.79,3575.79 ; v1(5507,4011) 5507,3958.34 R2.2 ; L1.2 C8.2 ; C8.2@5577.75,3232.25 C8.2 ; v2(5683,3212) 5662.75,3232.25 C8.2 ; R4.2 6124,3548 v2(6164,3588) 6240.68,3588 D1.2
  other v3: 5457,3580
+3V3A: C15.2 C16.2 L1.1 U3.22 | length 192.1
  Bottom Layer w10: U3.22 5433.77,3376.27 C16.2 C15.2 L1.1
+5V0: C27.2 R27.2 U4.2 USBC1.A4 USBC1.B9 | length 1626.2
  Top Layer w10: USBC1.B9 3193.42,3321.58 3208,3307 3208,3259 3383,3084 3514,3084 3600,3170 3600,3230 3731,3361 R27.2
  Top Layer w25: C27.2 3040.33,3598.26 3024,3581.93 3024,3572 3024,3501 3107,3418 3161.51,3418 3187.51,3392 USBC1.A4@3187.51,3351.4
  Top Layer w40: C27.2@3107,3598 U4.2
ANT: J1.1 U1.12 | length 81.9
  Top Layer w10: J1.1 5556.99,3257.97 U1.12
EXT_RX: J4.7 J4.10 U3.26 | length 1385.4
  Top Layer w9: J4.10 J4.7
  Top Layer w10: J4.7 4305,3267.61 4305,3236 4326,3215 4409,3215 4430,3194 4809,3194 4848,3155 5103,3155 5147,3199 5326,3199 v1(5333,3206)
  Bottom Layer w10: v1(5333,3206) U3.26
EXT_TX: J4.6 J4.11 U3.86 | length 1265.6
  Top Layer w9: J4.11 J4.6
  Top Layer w10: v1(4685,3544) 4877,3544 5057,3724 v1(5057,3773)
  Bottom Layer w10: J4.6 4345,3465.41 4345,3495 4424,3574 4655,3574 v1(4685,3544) ; v1(5057,3773) 5057.41,3773.41 U3.86
EXTINT: R12.1 U2.4 U3.35 | length 1949.7
  Top Layer w10: R12.1@6274.66,3761 6274.66,3743.34 6290,3728 6368,3728 6379.67,3716.33 U2.4@6379.67,3676.16 ; v1(6379,3600) 6379.67,3600.67 U2.4
  Bottom Layer w10: U3.35 5155.84,3192.84 5144,3181 5144,3151 5237,3058 5699,3058 5962,3321 5962,3480 5980,3498 6277,3498 v1(6379,3600)
GND: BT1.- C1.1 C2.1 C4.1 C5.1 C6.1 C7.2 C8.1 C9.1 C10.1 C11.1 C12.1 C13.1 C14.1 C15.1 C16.1 C17.1 C18.1 C19.1 C20.1 C21.1 C22.1 C23.1 C24.1 C26.1 C27.1 C29.1 C30.1 C31.1 D2.1 D4.1 D6.2 J1.2 J2.2 J4.2 J4.15 Q1.2 Q2.2 R17.1 R19.1 R20.1 R21.1 R25.1 R28.1 R29.1 SW1.3 SW1.4 SW2.1 U1.9 U1.10 U2.10 U2.12 U2.13 U2.24 U3.10 U3.19 U3.20 U3.27 U3.49 U3.74 U3.99 U4.7 USBC1.0 USBC1.1 USBC1.2 USBC1.3 USBC1.A1 USBC1.A12 USBC1.B1 USBC1.B12 | length 2382.9
  Top Layer w9: J4.15@4095.1,3796.51 J4.2@4275.1,3796.51 ; U2.12 5958.41,3626.9 5966.31,3619 6037,3619 6045.02,3627.02 U2.10
  Top Layer w10: v3(3633.1,3196.83) 3633.16,3196.77 C23.1@3633.16,3160.22 ; SW1.4@3699.42,3265 SW1.4 SW1.3
  Bottom Layer w8: C17.1 5479.25,3439.25 v3(5491,3451)
  Bottom Layer w9: U3.74 4852.02,3769.98 v1(4856,3766) ; v3(4860,3190) 4880.24,3210.24 U3.49 ; U3.27 5313.32,3218.2 5301,3205.89 5301,3191.46 C13.1 ; C22.1 5788.66,3559.66 v3(5802,3573)
  Bottom Layer w10: v2(4340,3140) 4341,3141 4405,3141 4429,3117 ; R25.1 4688.44,3414 v3(4725,3414) ; v3(4734.79,3849.79) C11.1 4751.32,3827.79 C12.1 ; C10.1 4837.67,3212.33 v3(4860,3190) ; C18.1 v3(4989.88,3179.79) ; Q1.2 5147.36,4006.36 v1(5161,4020) ; R29.1 5274,3985.04 v1(5274,4015) ; U3.99 5313.32,3687.32 v3(5313,3687) 5313,3657 5357.5,3612.5 U3.10 ; C13.1 5355,3173 v3(5358,3176) ; C14.1 5397.29,3893.71 v3(5412,3879) ; C14.1@5371.33,3891.51 C14.1@5371.41,3891.59 ; U3.20 U3.19 5454.86,3435.33 C17.1 ; C16.1 C15.1 5489.79,3284.33 5489.79,3244.25 5501.79,3232.25 C8.1 ; C16.1@5458.79,3310.11 5458.79,3278.22 5473.21,3263.79 v2(5489.79,3263.79) ; C9.1 5496.79,3612.25 v3@5496.79,3575.79 ; C20.1 v3(5576.79,3659.79) ; C19.1 v3(5577.79,3888.79) ; C21.1 5567.84,3534.74 5578.79,3523.79 5578.79,3507.79 v3(5577.79,3506.79) ; Q2.2 5758.64,4008.36 v1(5759,4008) ; v2(6326,3417) 6326,3386 6340,3372 6366.46,3372 C6.1 ; BT1.- v2(6527,3325)
  other v1: 5173,3085 5428,3102 5698,3123 5809,3208 3996,3265 5859,3357 3427,3405 3922,3412 3264,3445 3316,3498 3370,3498 3055,3528 3316,3530.5 3370,3530.5 3316,3563.5 3370,3563.5 3316,3596 3370,3596 3316,3628 3370,3628 5807,3751 5941.94,3946.53 6061,3947 6123,3966 5790,3970 5855,3989
  other v2: 5959,3119 3510,3155.27 6567,3155 3054,3156.27 3510,3321 3054,3322 5812,3498 3726,3579 3726,3623 3588,3655 5888,3697 5798,3702 3357,3777 4505,3777 3891.37,3981.48
  other v3: 3694,3228 4049,3547 5497,3579
  other v4: 3222,3756 3294,3792 3203,3873
GPS_NEN: Q3.1 R26.1 U3.16 | length 1465.3
  Top Layer w8: v1(5526,3452) 5545,3433 6207,3433 6228,3454 6511.96,3454 R26.1 6623.96,3253.65 Q3.1
  Bottom Layer w8: U3.16 5483.62,3494.38 v1(5526,3452)
GPS_RX: R14.1 U2.21 U3.33 | length 1648
  Top Layer w10: v1(5209,3174) 5261,3122 5354,3122 5439,3207 5439,3289 5564,3414 6203.85,3414 6379.67,3238.18 U2.21 6379.67,3122.16 R14.1@6372.5,3115
  Bottom Layer w10: U3.33 5195.21,3187.7 v1@5208.91,3174
GPS_TX: R13.1 U2.20 U3.34 | length 1655
  Top Layer w10: v1(5174,3172) 5243,3103 5362,3103 5459,3200 5459,3282 5573,3396 6194.54,3396 6336.36,3254.18 U2.20 6336.36,3142.7 R13.1
  Bottom Layer w10: v1(5174,3172) 5176,3174 5176,3255.72 U3.34
GPS_VIN: C1.2 Q3.3 U2.23 | length 385.2
  Top Layer w8: U2.23 6467,3193.12 6467,3142 6494,3115 C1.2 6495,3108 6495,3085 6503,3077 6576,3077 6594.98,3095.98 6594.98,3236 6586.98,3244 Q3.3
MIC_IN: U1.18 U3.29 | length 965.9
  Top Layer w10: U1.18 4622.85,3375 5245,3375 v1(5272,3402)
  Bottom Layer w10: v1@5271.95,3401.95 5271.95,3258.2 U3.29
NRST: R30.2 SW1.1 U3.14 | length 2101.5
  Top Layer w8: SW1.1 4124.83,3119.17 4147,3097 v1(4293,3097)
  Top Layer w10: v1(4423,3506) 4458,3471 5250,3471 v1(5313,3534) ; v1(4427,3284) v1(4427,3388)
  Bottom Layer w10: v1(4423,3506) 4405.34,3488.34 4405.34,3467 R30.2 4410,3462.34 4410,3428 4428,3410 4428,3389 v1(4427,3388) ; v1(4427,3284) 4378,3235 4358,3235 4334,3211 4334,3183 4293,3142 v1(4293,3097) 4320,3070 4455,3070 4479,3094 4479,3117 ; v1(5313,3534) 5393.77,3534 U3.14
OSC16_IN: C21.2 U3.12 X2.1 | length 251.6
  Bottom Layer w10: U3.12 5428.46,3573.12 5445.79,3555.79 5517.79,3555.79 5539.72,3577.73 C21.2@5554.46,3577.73 ; C21.2 C21.2@5554.46,3577.73 ; X2.1 C21.2@5554.46,3577.73
OSC16_OUT: R16.2 U3.13 | length 291.9
  Bottom Layer w10: U3.13 5425.14,3553.44 5457.79,3520.79 5520.68,3520.79 5596.27,3445.2 R16.2@5641.08,3445.2
OSC32_IN: C19.2 U3.8 X1.1 | length 379.1
  Bottom Layer w10: U3.8 5425.86,3651.87 5446.79,3672.79 5446.79,3859.79 5475.79,3888.79 C19.2 5500.33,3824.44 X1.1
OSC32_OUT: C20.2 U3.9 X1.2 | length 180.7
  Bottom Layer w10: U3.9 5429.17,3632.18 5456.79,3659.79 C20.2 5499.33,3723.05 X1.2
PPS: R5.1 U2.3 | length 94.1
  Top Layer w10: R5.1 6406.66,3753 6406.66,3732.99 6422.98,3716.67 U2.3
PPS_OUT: R5.2 R8.1 U3.54 | length 2466.6
  Top Layer w10: v1(4916,3119) 4962.11,3119 R8.1 4962.36,3078 4983.36,3057 5736,3057 ; 5736.81,3057.81 5750,3071 5875,3071 5912,3108 5912,3232 v1(6000,3320) ; v1(6000,3469) 6168,3637 6168,3768 6191,3791 6309.34,3791 R5.2
  Bottom Layer w10: U3.54 4750,3376.27 4740,3366.27 4740,3201 4822,3119 v1(4916,3119) ; v1(6000,3320) v1(6000,3469)
PTT: Q1.3 R1.1 U1.5 | length 275.6
  Top Layer w10: v1(5144,3903) 5144,3938.44 5163,3957.44 U1.5
  Bottom Layer w10: R1.1@4986.5,3920 Q1.3@5091.64,3920 ; Q1.3 Q1.3@5091.64,3920 ; v1(5144,3903) 5140,3903 5126,3917 5094.64,3917 Q1.3@5091.64,3920
PTT_IN: Q1.1 U3.25 | length 1007
  Top Layer w10: v1(5089,4015) 5089,3841 5200,3730 v1(5200,3508) ; v1(5200,3426) 5206,3432 5312,3432 5351,3393 5351,3335 v1(5326,3310)
  Bottom Layer w10: Q1.1 5080.36,4006.36 v1(5089,4015) ; v1(5200,3426) v1(5200,3508) ; v1(5326,3310) 5333.22,3317.22 U3.25
PWR_LVL: Q2.3 R2.1 U1.7 | length 255
  Top Layer w10: U1.7 5605.56,3957.44 5621,3942 v1(5621,3900)
  Bottom Layer w10: R2.1 5567.66,3953.34 v1(5621,3900) 5621,3903.64 5639,3921.64 Q2.3
PWR_LVL_IN: Q2.1 U3.31 | length 1168.6
  Top Layer w10: v1(5281,3659) 5483,3659 5647,3823 5647,3935 5677,3965 v1(5677,4019)
  Bottom Layer w10: U3.31 5234.58,3294.7 5158,3371.27 5158,3536 v1(5281,3659) ; Q2.1 5666.36,4008.36 v1(5677,4019)
RESET_N: R4.1 U2.8 | length 313.8
  Top Layer w10: v1(5964,3573) 5984,3593 6089,3593 6131.64,3635.64 U2.8
  Bottom Layer w10: v1(5964,3573) 5989,3548 R4.1
RF_IN: D4.2 J2.1 L2.1 U2.11 | length 197
  Top Layer w11.54: D4.2 L2.1 ; J2.1 6001.01,3751.44 L2.1 ; U2.11 6001.44,3674.44 L2.1
SLEEP: R15.1 U1.6 U3.30 | length 887
  Top Layer w10: v1(5254,3552) 5254,3825.05 U1.6 5454.44,3957.44 v1(5455,3958)
  Bottom Layer w10: v1(5254,3552) 5239,3537 5239,3351 5254,3336 5254,3256.46 U3.30 ; R15.1@5405.5,3958 v1(5455,3958)
SWCLK: U3.76 | length 1110.9
  Top Layer w10: v1(4555,3498) v1(4924,3498)
  Bottom Layer w10: 4479,3167 4480,3168 4480,3254 4555,3329 v1(4555,3498) ; U3.76 4860,3850.12 4860,3801 4924,3737 v1(4924,3498)
SWDIO: U3.72 | length 896.4
  Top Layer w10: v1(4742,3599) 4841,3599 4879,3637 v1(4879,3731)
  Bottom Layer w10: 4529,3167 4529,3240 4587,3298 4587,3475 4627,3515 4712,3515 4742,3545 v1(4742,3599) ; U3.72 4878.61,3730.61 v1(4879,3731)
SWO: U3.89 | length 1228.7
  Top Layer w10: v1(4505,3514) 4515,3524 4603,3524 4613,3514 4881,3514 5076,3709 v1(5116,3709)
  Bottom Layer w10: 4429,3167 4429,3238 4515,3324 4515,3504 v1(4505,3514) ; v1(5116,3709) 5116,3850.22 U3.89
USB_BOOT_EN: D6.6 J4.3 J4.14 SW2.2 U3.69 | length 1177
  Top Layer w8: v1(3894,3515) 3926.84,3515 D6.6
  Top Layer w9: J4.14@4095.1,3696.51 J4.3@4275.1,3696.51
  Top Layer w10: v1(3894,3666.52) SW2.2 4065.11,3666.52 J4.14@4095.1,3696.51 ; J4.3 4385.49,3696.51 4449,3633 v1(4450,3633)
  Bottom Layer w10: v1@3894,3518 3887,3518 3866,3539 3866,3591 3894,3619 v1(3894,3666.52) ; v1(4450,3633) 4709,3633 4747.55,3671.55 U3.69
USB_VBUS_IN: R27.1 R28.2 U3.68 | length 1008.3
  Top Layer w8: R27.1 R28.2 4016.04,3432 v1(4045,3432)
  Bottom Layer w8: 4163,3396 4211,3396
  Bottom Layer w9: 4109,3450 4163,3396 ; 4211,3396 4268,3453
  Bottom Layer w10: v1(4045,3432) 4063,3450 4109,3450 ; 4268,3453 4298,3453 4323,3478 4323,3496 4431,3604 4714,3604 4761.87,3651.87 U3.68
USBD_N: D6.3 J4.4 J4.13 R23.1 USBC1.A7 USBC1.B7 | length 1878
  Top Layer w8: v1(3250,3411) 3252.47,3408.53 USBC1.B7 ; v1(3294,3395) 3291.84,3392.84 USBC1.A7 3291.84,3319.82 3289,3316.98 3289,3312.98 3364.98,3237 3518,3237 3707,3426 3798,3426 3866,3494 3866,3558 3900,3592 3962,3592 3981.41,3572.59 D6.3 4072.18,3572.59 J4.13 ; J4.13@4095.1,3596.51 J4.4@4275.1,3596.51
  Bottom Layer w8: v1(3250,3411) 3266,3395 v1(3294,3395) ; J4.4 4301.94,3570.67 4313.26,3570.67 4443.59,3701 4572,3701 4580,3709 4602,3709 4638.21,3672.79 R23.1
USBD_P: D6.1 J4.5 J4.12 R22.2 USBC1.A6 USBC1.B6 | length 1885.4
  Top Layer w8: USBC1.B6 3311.53,3381.73 3321,3391.2 3321,3409.09 3312.11,3417.98 3284.98,3417.98 3272,3405 3272,3351.57 USBC1.A6 3272.16,3319.82 3275,3316.98 3275,3307.18 3359.18,3223 3523.8,3223 3712.8,3412 3803.8,3412 3878.8,3487 3948,3487 3982.41,3521.41 D6.1 4071.2,3521.41 J4.12 ; J4.12@4095.1,3496.51 J4.5@4275.1,3496.51 ; v1(4591,3687) 4613,3709 v1(4613,3729)
  Bottom Layer w8: J4.5 4276.1,3513.71 4449.39,3687 v1(4591,3687) ; v1(4613,3729) 4613.21,3728.79 R22.2
V_BCKP: BT1.+ C6.2 R7.1 U2.22 | length 254.6
  Top Layer w10: U2.22 v2(6423,3259)
  Bottom Layer w10: R7.1 6367.46,3325 C6.2 ; C6.2@6369,3325 BT1.+ v2@6423.47,3259
VCAP: C18.2 U3.48 | length 76.5
  Bottom Layer w10: U3.48 4900.23,3255.9 C18.2
VCC_RF: R3.2 U2.9 | length 92.5
  Top Layer w11.54: U2.9 6088.33,3717.67 R3.2
VHF_RX: U1.16 U3.23 | length 634.8
  Top Layer w10: U1.16 4921.24,3323 5306,3323 5319,3336 5319,3386 v1(5316,3389)
  Bottom Layer w10: v1(5316,3389) 5349,3356 5393.43,3356 U3.23
VHF_TX: U1.17 U3.24 | length 757.7
  Top Layer w10: U1.17 4764.06,3341.02 5278.02,3341.02 v1(5296,3359)
  Bottom Layer w10: v1(5296,3359) 5318.3,3336.7 5393.82,3336.7 U3.24
VREF+: C17.2 U3.21 | length 64.9
  Bottom Layer w10: U3.21 5394.39,3396.33 C17.2
VSYS: J4.8 J4.9 R24.2 | length 775.4
  Top Layer w9: J4.9@4095.1,3196.51 J4.8@4275.1,3196.51
  Top Layer w10: v1(4457,3345) 4475,3363 4557,3363 v1(4634,3440)
  Bottom Layer w10: J4.8 4291.51,3196.51 4440,3345 v1(4457,3345) ; v1@4635,3440 4643,3448 4643,3473 4659.72,3489.72 4734.99,3489.72 R24.2
VSYS_IN: R24.1 R25.2 U3.58 | length 118.2
  Bottom Layer w10: R25.2 4735.58,3454.53 4735.99,3454.94 R24.1 4799.17,3454.64 U3.58
"": D6.4 U1.1 U1.2 U1.3 U1.4 U1.11 U1.13 U1.14 U1.15 U1.P2 U1.P3 U2.1 U2.5 U2.6 U2.7 U2.14 U2.15 U2.16 U2.17 U2.18 U2.19 U3.1 U3.2 U3.3 U3.4 U3.5 U3.6 U3.7 U3.15 U3.17 U3.18 U3.32 U3.36 U3.38 U3.39 U3.40 U3.41 U3.42 U3.43 U3.44 U3.45 U3.46 U3.47 U3.51 U3.52 U3.53 U3.55 U3.56 U3.57 U3.59 U3.60 U3.61 U3.62 U3.63 U3.64 U3.65 U3.66 U3.67 U3.77 U3.78 U3.79 U3.80 U3.81 U3.82 U3.83 U3.84 U3.85 U3.87 U3.88 U3.90 U3.91 U3.92 U3.93 U3.95 U3.96 U3.97 U3.98 U4.3 USBC1.A8 USBC1.A9 USBC1.B4 USBC1.B8 X2.2 X2.4

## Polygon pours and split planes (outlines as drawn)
GND on Top Layer (solid, remove dead copper, pour order 0): 3000,3033 6714,3033 6714,4049 3000,4049
GND on Inner1 (split plane): 3452.28,3326.16 3486.1,3326.16 3486.1,3316.16 3452.28,3316.16
GND on Inner1 (split plane): 3447.28,3321.16 3447.28,3370.73 3457.28,3370.73 3457.28,3321.16
GND on Inner1 (split plane): 3457.28,3321.16 3457.28,3271.59 3447.28,3271.59 3447.28,3321.16
GND on Inner1 (split plane): 4091.1,3796.51 4091.1,3836.24 4101.1,3836.24 4101.1,3796.51
GND on Inner1 (split plane): 4101.1,3796.51 4101.1,3756.78 4091.1,3756.78 4091.1,3796.51
GND on Inner1 (split plane): 4096.1,3801.51 4135.83,3801.51 4135.83,3791.51 4096.1,3791.51
GND on Inner1 (split plane): 4056.37,3801.51 4096.1,3801.51 4096.1,3791.51 4056.37,3791.51
GND on Inner1 (split plane): 3418.46,3161.59 3452.28,3161.59 3452.28,3151.59 3418.46,3151.59
GND on Inner1 (split plane): 3452.28,3161.59 3486.1,3161.59 3486.1,3151.59 3452.28,3151.59
GND on Inner1 (split plane): 3447.28,3156.59 3447.28,3202.23 3457.28,3202.23 3457.28,3156.59
GND on Inner1 (split plane): 3457.28,3156.59 3457.28,3110.96 3447.28,3110.96 3447.28,3156.59
GND on Inner1 (split plane): 3077.9,3326.16 3111.72,3326.16 3111.72,3316.16 3077.9,3316.16
GND on Inner1 (split plane): 3106.72,3321.16 3106.72,3370.73 3116.72,3370.73 3116.72,3321.16
GND on Inner1 (split plane): 3116.72,3321.16 3116.72,3271.59 3106.72,3271.59 3106.72,3321.16
GND on Inner1 (split plane): 3077.9,3161.59 3111.72,3161.59 3111.72,3151.59 3077.9,3151.59
GND on Inner1 (split plane): 3111.72,3161.59 3145.54,3161.59 3145.54,3151.59 3111.72,3151.59
GND on Inner1 (split plane): 3106.72,3156.59 3106.72,3202.23 3116.72,3202.23 3116.72,3156.59
GND on Inner1 (split plane): 3116.72,3156.59 3116.72,3110.96 3106.72,3110.96 3106.72,3156.59
GND on Inner1 (split plane): 4271.1,3796.51 4271.1,3836.24 4281.1,3836.24 4281.1,3796.51
GND on Inner1 (split plane): 4281.1,3796.51 4281.1,3756.78 4271.1,3756.78 4271.1,3796.51
GND on Inner1 (split plane): 4276.1,3801.51 4315.83,3801.51 4315.83,3791.51 4276.1,3791.51
GND on Inner1 (split plane): 4236.37,3801.51 4276.1,3801.51 4276.1,3791.51 4236.37,3791.51
+3V3 on Inner2 (split plane): 4091.1,3896.51 4091.1,3936.24 4101.1,3936.24 4101.1,3896.51
+3V3 on Inner2 (split plane): 4101.1,3896.51 4101.1,3856.78 4091.1,3856.78 4091.1,3896.51
+3V3 on Inner2 (split plane): 4096.1,3901.51 4135.83,3901.51 4135.83,3891.51 4096.1,3891.51
+3V3 on Inner2 (split plane): 4056.37,3901.51 4096.1,3901.51 4096.1,3891.51 4056.37,3891.51
+3V3 on Inner2 (split plane): 4271.1,3896.51 4271.1,3936.24 4281.1,3936.24 4281.1,3896.51
+3V3 on Inner2 (split plane): 4281.1,3896.51 4281.1,3856.78 4271.1,3856.78 4271.1,3896.51
+3V3 on Inner2 (split plane): 4276.1,3901.51 4315.83,3901.51 4315.83,3891.51 4276.1,3891.51
+3V3 on Inner2 (split plane): 4236.37,3901.51 4276.1,3901.51 4276.1,3891.51 4236.37,3891.51

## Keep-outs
Board Outline Layer:
  lines w10 net "": 3002,3041 6702.78,3041 6702.78,3808.72 ; 3002,3041 3002,3041 ; 3002,3041 3002,4044.94 6190.97,4044.94 6190.97,3808.72 6702.78,3808.72 ; 6702.78,3808.72 6702.78,3808.72

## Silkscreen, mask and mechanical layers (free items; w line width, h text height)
Top Silkscreen Layer:
  text "USB" at 4029.51,4000.99 h29.2
  text "BOOT" at 4028.22,3956.99 h29.2
  text "MCU RST" at 3712.38,3323.99 h29.2
  text "3V3" at 4730.51,3054.99 h29.2
  text "PPS" at 5023.51,3054.99 h29.2
Bottom Silkscreen Layer:
  text "Project CETI" at 6651.96,3172.99 h29.2
  text "Recovery Board V3" at 6645.55,3121.99 h29.2
  text "August 2023" at 6653.25,3067.99 h29.2
  text "DEBUG" at 4543.94,3054.99 h29.2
